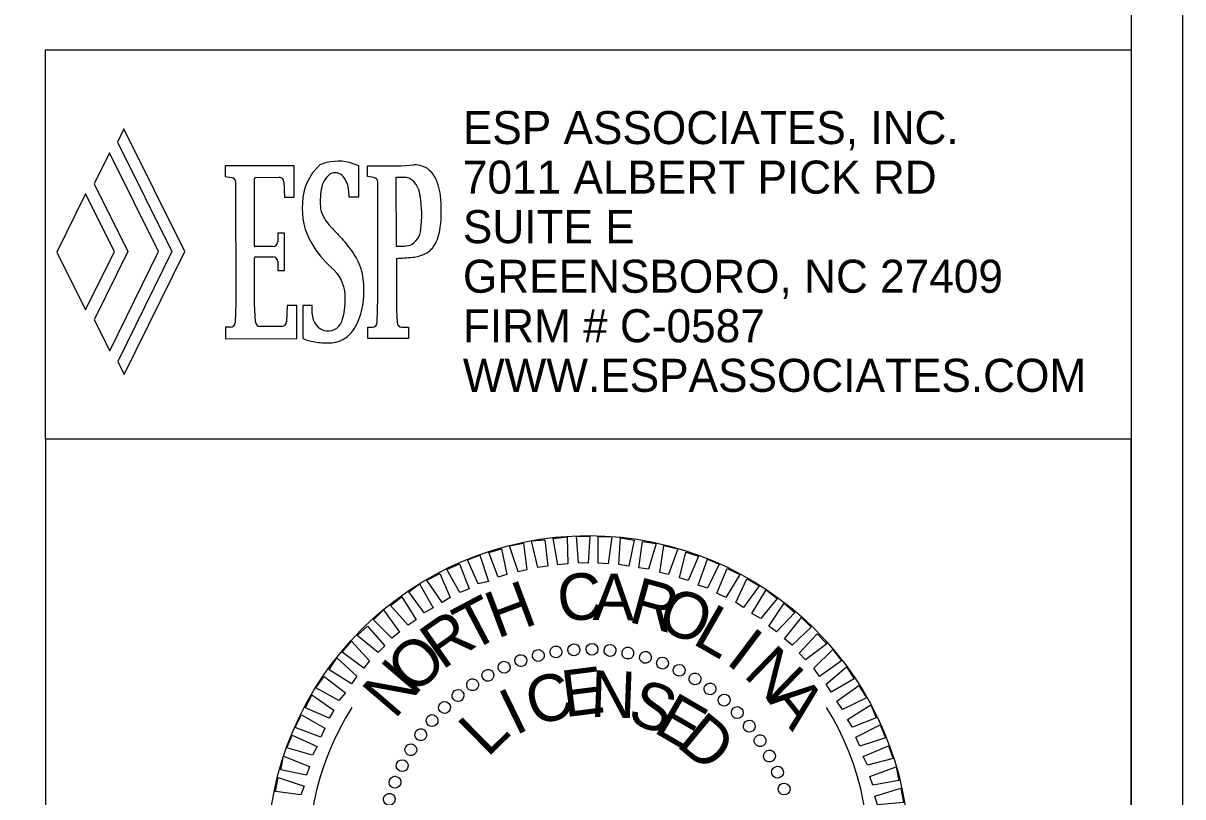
# Model space of a CAD drawing. Extents: x 265553 to 275568, y 168312 to 173522.
# Drawn here: x 268190.7 to 268471.5, y 172334.2 to 172521.6 of the extents above; entities that cross this region are included whole.
import ezdxf

# ---------------------------------------------------------------- set-up
doc = ezdxf.new("R2010")
doc.units = 0
for name, color, linetype in [('Default', 7, 'Continuous'), ('Geotech Sheets and Borders Cell', 7, 'Continuous'), ('Prop Strc Sect_ Border - minor', 7, 'Continuous'), ('Scratch_Level_0', 7, 'Continuous'), ('Scratch_Level_6', 7, 'Continuous'), ('Sheet Plot Border Inside CELL', 7, 'Continuous'), ('Sheet Professional Seal CELL', 7, 'Continuous')]:
    doc.layers.add(name, color=color, linetype=linetype)

msp = doc.modelspace()

# ---------------------------------------------------------------- linework, layer by layer
at = {"layer": 'Default'}
for p, q in [((268271.91, 172487.05), (268269.65, 172487.89)), ((268282.16, 172487.07), (268285.23, 172487.25)), ((268256.25, 172487.04), (268239.59, 172487.02)), ((268239.59, 172487.02), (268239.6, 172484.44)), ((268239.6, 172484.44), (268241.14, 172484.21)), ((268256.26, 172479.43), (268256.25, 172487.04)), ((268271.92, 172479.56), (268271.91, 172487.05)), ((268274.08, 172487.06), (268282.16, 172487.07)), ((268274.08, 172484.48), (268274.08, 172487.06)), ((268275.58, 172484.21), (268274.08, 172484.48)), ((268281.02, 172484.29), (268283.24, 172484.29)), ((268281.04, 172467.5), (268281.02, 172484.29)), ((268242.11, 172483.07), (268242.14, 172453.95)), ((268246.69, 172467.69), (268246.67, 172483.94)), ((268246.98, 172484.25), (268252.66, 172484.26)), ((268253.81, 172483.15), (268253.94, 172479.43)), ((268276.58, 172455.06), (268276.55, 172483.05)), ((268286.3, 172481.53), (268286.83, 172479.69)), ((268253.94, 172479.43), (268256.26, 172479.43)), ((268269.48, 172481.06), (268269.53, 172479.55)), ((268269.53, 172479.55), (268271.92, 172479.56)), ((268253.95, 172470.75), (268252.29, 172470.75)), ((268252.29, 172470.75), (268252.29, 172468.62)), ((268253.96, 172461.69), (268253.95, 172470.75)), ((268251.14, 172467.48), (268246.91, 172467.47)), ((268283, 172467.5), (268281.04, 172467.5)), ((268284.29, 172467.77), (268283, 172467.5)), ((268246.7, 172453.54), (268246.69, 172464.8)), ((268246.91, 172465.02), (268251.15, 172465.02)), ((268281.04, 172464.65), (268281.05, 172452.1)), ((268252.3, 172463.88), (268252.3, 172461.69)), ((268252.3, 172461.69), (268253.96, 172461.69)), ((268242.14, 172453.95), (268241.98, 172449.06)), ((268246.9, 172449.25), (268246.7, 172453.54)), ((268276.38, 172449.1), (268276.58, 172455.06)), ((268254.56, 172453.18), (268254.44, 172449.28)), ((268256.95, 172453.18), (268254.56, 172453.18)), ((268256.95, 172445.19), (268256.95, 172453.18)), ((268260.63, 172453.19), (268258.36, 172453.18)), ((268258.36, 172453.18), (268258.37, 172445.19)), ((268260.63, 172451.19), (268260.63, 172453.19)), ((268281.05, 172452.1), (268281.22, 172449.08)), ((268240.84, 172447.95), (268239.63, 172447.95)), ((268239.63, 172447.95), (268239.64, 172445.17)), ((268253.29, 172448.17), (268248.05, 172448.17)), ((268274.12, 172445.21), (268274.12, 172447.99)), ((268274.12, 172447.99), (268275.23, 172447.99)), ((268282.36, 172448), (268283.96, 172448)), ((268283.96, 172448), (268283.96, 172445.22)), ((268239.64, 172445.17), (268256.95, 172445.19)), ((268283.96, 172445.22), (268274.12, 172445.21))]:
    msp.add_line(p, q, dxfattribs=at)
for points in [[(268213.46, 172492.81), (268226.67, 172466.31), (268213.55, 172439.66), (268215.14, 172436.47), (268229.83, 172466.32), (268215.03, 172496.01), (268213.46, 172492.81)], [(268207.84, 172482.69), (268216.02, 172466.28), (268207.88, 172449.75), (268211.6, 172442.27), (268223.43, 172466.3), (268211.52, 172490.18), (268207.84, 172482.69)], [(268205.74, 172480.29), (268198.78, 172466.15), (268205.77, 172452.13), (268212.73, 172466.27), (268205.74, 172480.29)]]:
    msp.add_lwpolyline(points, dxfattribs=at)
for centre, radius, start, end in [((268271.1, 172477.8), 12.79, 132.277, 178.7717), ((268267.07, 172476.27), 11.9, 77.4945, 112.607), ((268285.56, 172481.83), 5.43, 34.4894, 93.4478), ((268268.49, 172480.56), 5.7, 127.7022, 172.2101), ((268266.19, 172482.77), 2.59, 40.3385, 117.3766), ((268263.94, 172480.86), 5.53, 2.0028, 40.3385), ((268282.49, 172480.38), 3.99, 16.8704, 79.0876), ((268278.26, 172478.17), 13.56, 7.0821, 29.7759), ((268240.97, 172483.07), 1.15, 0.0607, 81.368), ((268246.98, 172483.94), 0.31, 90.0607, 180.0607), ((268252.67, 172483.11), 1.15, 1.9943, 90.0607), ((268275.37, 172483.05), 1.18, 0.0607, 79.8192), ((268279.81, 172478.37), 17.22, 170.1104, 185.809), ((268258.92, 172475.19), 28.27, 352.8067, 9.1634), ((268256.04, 172476.16), 35.87, 353.4945, 5.8911), ((268274.23, 172476.51), 15.99, 174.413, 211.2268), ((268272.23, 172479.19), 9.9, 195.0144, 224.5602), ((268819.02, 172983), 753.4, 222.68215, 223.01817), ((268282.29, 172472.02), 4.69, 295.2092, 355.4805), ((268281.01, 172473.27), 10.73, 328.9362, 353.7339), ((268246.91, 172467.69), 0.22, 180.0607, 270.0607), ((268251.14, 172468.62), 1.15, 270.0607, 0.0607), ((268281.1, 172480.17), 23.76, 210.18, 228.2816), ((268251.2, 172453.16), 23.23, 30.8042, 43.0163), ((268285.62, 172470.63), 5.42, 295.5502, 327.7187), ((268246.91, 172464.8), 0.22, 90.0607, 180.0607), ((268251.15, 172463.87), 1.15, 0.0607, 90.0607), ((268259.62, 172458.06), 13.48, 9.1866, 31.2488), ((268278.09, 172537.43), 72.85, 272.3182, 275.4374), ((268284.16, 172473.67), 8.8, 275.4374, 295.5502), ((268259.54, 172455.38), 9.09, 3.0107, 50.83), ((268249.59, 172456.8), 23.59, 356.494, 8.3188), ((268252.99, 172454.57), 15.68, 343.132, 4.7325), ((268256.42, 172456.03), 16.73, 338.2327, 357.7166), ((268264.73, 172451.14), 4.1, 179.1725, 260.7014), ((268240.83, 172449.1), 1.15, 270.0607, 358.0948), ((268248.05, 172449.32), 1.15, 183.0592, 270.0607), ((268253.29, 172449.32), 1.15, 270.0607, 358.1271), ((268264.52, 172450.59), 3.52, 262.5493, 350.6871), ((268262.09, 172453.45), 10.51, 312.5245, 339.8341), ((268275.23, 172449.14), 1.15, 270.0607, 358.0948), ((268282.36, 172449.14), 1.15, 183.0592, 270.0607), ((268263.52, 172458.35), 14.13, 248.6025, 262.4993), ((268264.81, 172451.31), 7.12, 274.5621, 307.9936), ((268264.2, 172463.79), 19.61, 262.6129, 273.4517)]:
    msp.add_arc(centre, radius, start, end, dxfattribs=at)
at = {"layer": 'Geotech Sheets and Borders Cell'}
msp.add_lwpolyline([(266959.02, 173192.58), (268459.02, 173192.58), (268459.02, 172142.58), (266959.02, 172142.58)], close=True, dxfattribs=at)
msp.add_lwpolyline([(268459.02, 172420.84), (268459.02, 172420.84), (268196.05, 172420.84), (268196.05, 172142.58), (268459.02, 172142.58), (268459.02, 172420.84)], dxfattribs=at)
at = {"layer": 'Scratch_Level_0'}
msp.add_ellipse((268327.53, 172319.79), major_axis=(45.09, 51.04), ratio=0.993455, start_param=1.731198, end_param=5.992706, dxfattribs=at)
at = {"layer": 'Scratch_Level_6'}
msp.add_lwpolyline([(268196.05, 172515.1), (268459.02, 172515.1), (268459.02, 172420.84), (268196.05, 172420.84)], close=True, dxfattribs=at)
msp.add_circle((268327.53, 172319.79), 77.7, dxfattribs=at)
msp.add_circle((268327.53, 172319.79), 77.7, dxfattribs=at)
at = {"layer": 'Sheet Plot Border Inside CELL'}
msp.add_lwpolyline([(266803.85, 172139.74), (268471.52, 172139.74), (268471.52, 173195.41), (266803.85, 173195.41)], close=True, dxfattribs=at)
at = {"layer": 'Sheet Professional Seal CELL'}
for p, q in [((268319.73, 172369.29), (268319.73, 172369.29)), ((268324.03, 172369.89), (268324.03, 172369.89)), ((268328.43, 172369.99), (268328.43, 172369.99)), ((268332.83, 172369.69), (268332.83, 172369.69)), ((268311.13, 172367.29), (268311.13, 172367.29)), ((268315.33, 172368.49), (268315.33, 172368.49)), ((268337.13, 172368.99), (268337.13, 172368.99)), ((268341.33, 172368.09), (268341.33, 172368.09)), ((268345.53, 172366.69), (268345.53, 172366.69)), ((268303.23, 172363.69), (268303.23, 172363.69)), ((268307.13, 172365.69), (268307.13, 172365.69)), ((268349.53, 172364.89), (268349.53, 172364.89)), ((268299.43, 172361.39), (268299.43, 172361.39)), ((268353.43, 172362.89), (268353.43, 172362.89)), ((268295.93, 172358.89), (268295.93, 172358.89)), ((268357.03, 172360.39), (268357.03, 172360.39)), ((268292.63, 172355.89), (268292.63, 172355.89)), ((268360.53, 172357.69), (268360.53, 172357.69)), ((268289.63, 172352.79), (268289.63, 172352.79)), ((268363.63, 172354.69), (268363.63, 172354.69)), ((268366.63, 172351.39), (268366.63, 172351.39)), ((268286.93, 172349.29), (268286.93, 172349.29)), ((268369.13, 172347.89), (268369.13, 172347.89)), ((268284.43, 172345.69), (268284.43, 172345.69)), ((268371.43, 172344.09), (268371.43, 172344.09)), ((268282.43, 172341.79), (268282.43, 172341.79)), ((268373.43, 172340.19), (268373.43, 172340.19)), ((268280.63, 172337.79), (268280.63, 172337.79)), ((268375.03, 172336.19), (268375.03, 172336.19))]:
    msp.add_line(p, q, dxfattribs=at)
for points in [[(268325.13, 172390.89), (268324.63, 172397.39), (268327.93, 172397.29), (268327.53, 172390.79)], [(268329.93, 172390.79), (268329.93, 172397.29), (268333.23, 172397.19), (268332.33, 172390.69)], [(268310.53, 172388.69), (268308.43, 172394.99), (268311.83, 172395.69), (268312.63, 172389.19)], [(268315.33, 172389.79), (268313.73, 172396.19), (268317.03, 172396.49), (268317.73, 172390.09)], [(268320.13, 172390.39), (268319.03, 172396.79), (268322.43, 172397.19), (268322.53, 172390.69)], [(268334.93, 172390.49), (268335.33, 172396.99), (268338.63, 172396.39), (268337.33, 172390.09)], [(268339.73, 172389.69), (268340.63, 172396.09), (268343.93, 172395.59), (268342.13, 172389.39)], [(268344.83, 172388.59), (268345.83, 172395.09), (268349.23, 172394.29), (268346.93, 172388.09)], [(268300.83, 172385.79), (268298.23, 172391.59), (268301.23, 172392.79), (268303.33, 172386.39)], [(268305.73, 172387.39), (268303.43, 172393.39), (268306.53, 172394.29), (268307.83, 172388.09)], [(268349.63, 172387.29), (268351.13, 172393.49), (268354.23, 172392.49), (268351.73, 172386.59)], [(268354.13, 172385.49), (268356.43, 172391.79), (268359.23, 172390.59), (268356.43, 172384.79)], [(268296.43, 172383.69), (268293.23, 172389.29), (268296.33, 172390.69), (268298.63, 172384.59)], [(268358.63, 172383.59), (268361.13, 172389.49), (268364.23, 172388.09), (268360.83, 172382.49)], [(268292.13, 172381.29), (268288.43, 172386.69), (268291.53, 172388.29), (268294.03, 172382.49)], [(268363.23, 172381.29), (268365.93, 172386.99), (268368.93, 172385.29), (268365.13, 172380.09)], [(268287.73, 172378.79), (268284.03, 172383.89), (268286.63, 172385.79), (268289.93, 172379.99)], [(268367.13, 172378.59), (268370.63, 172384.39), (268373.23, 172382.29), (268369.33, 172377.39)], [(268283.93, 172375.79), (268279.63, 172380.59), (268282.33, 172382.69), (268285.83, 172377.09)], [(268371.23, 172375.59), (268374.93, 172381.09), (268377.53, 172378.89), (268373.13, 172374.19)], [(268279.93, 172372.69), (268275.53, 172377.09), (268277.93, 172379.49), (268281.83, 172374.09)], [(268375.03, 172372.49), (268379.13, 172377.69), (268381.53, 172375.29), (268376.93, 172370.99)], [(268276.63, 172369.19), (268271.53, 172373.29), (268274.03, 172375.59), (268278.23, 172370.79)], [(268378.63, 172368.99), (268382.93, 172373.69), (268385.33, 172371.29), (268380.13, 172367.39)], [(268273.13, 172365.39), (268267.93, 172369.29), (268270.13, 172371.89), (268274.53, 172367.19)], [(268382.13, 172365.39), (268386.73, 172369.89), (268388.83, 172367.19), (268383.53, 172363.39)], [(268270.13, 172361.59), (268264.73, 172364.99), (268266.63, 172367.89), (268271.43, 172363.49)], [(268385.13, 172361.49), (268390.03, 172365.69), (268391.93, 172362.79), (268386.33, 172359.59)], [(268267.13, 172357.59), (268261.53, 172360.59), (268263.53, 172363.39), (268268.73, 172359.39)], [(268387.73, 172357.39), (268393.03, 172361.19), (268394.93, 172358.19), (268389.13, 172355.39)], [(268264.73, 172353.29), (268259.03, 172355.79), (268260.53, 172358.89), (268265.93, 172355.19)], [(268390.33, 172352.99), (268395.93, 172356.49), (268397.23, 172353.39), (268391.53, 172351.09)], [(268262.73, 172348.69), (268256.53, 172350.99), (268258.03, 172354.09), (268263.73, 172350.89)], [(268392.33, 172348.69), (268398.23, 172351.69), (268399.53, 172348.49), (268393.33, 172346.49)], [(268260.73, 172344.29), (268254.53, 172346.09), (268255.83, 172349.19), (268261.83, 172346.39)], [(268259.23, 172339.49), (268253.03, 172340.79), (268253.73, 172344.09), (268260.03, 172341.59)], [(268394.13, 172343.99), (268400.23, 172346.59), (268401.33, 172343.49), (268395.13, 172341.89)], [(268395.73, 172339.19), (268402.13, 172341.49), (268402.73, 172338.19), (268396.43, 172337.09)], [(268257.93, 172334.69), (268251.73, 172335.49), (268252.43, 172338.89), (268258.73, 172336.79)], [(268396.93, 172334.39), (268403.23, 172336.29), (268403.83, 172332.89), (268397.53, 172332.29)]]:
    msp.add_lwpolyline(points, close=True, dxfattribs=at)
for centre, major_axis in [((268315.4, 172368.46), (-0.35, 1.4)), ((268319.69, 172369.33), (-0.23, 1.42)), ((268324.03, 172369.83), (-0.1, 1.44)), ((268328.41, 172369.94), (0.03, 1.44)), ((268332.78, 172369.68), (0.15, 1.43)), ((268337.1, 172369.03), (0.27, 1.41)), ((268341.36, 172368.01), (0.4, 1.38)), ((268307.13, 172365.61), (-0.59, 1.32)), ((268311.2, 172367.22), (-0.47, 1.36)), ((268345.51, 172366.62), (0.52, 1.34)), ((268349.52, 172364.87), (0.63, 1.29)), ((268303.21, 172363.66), (-0.7, 1.26)), ((268353.37, 172362.79), (0.74, 1.23)), ((268299.48, 172361.37), (-0.81, 1.19)), ((268357.02, 172360.37), (0.85, 1.16)), ((268295.97, 172358.77), (-0.91, 1.12)), ((268360.44, 172357.65), (0.94, 1.09)), ((268292.69, 172355.87), (-1, 1.04)), ((268363.61, 172354.63), (1.04, 1)), ((268289.68, 172352.7), (-1.09, 0.94)), ((268366.51, 172351.36), (1.12, 0.91)), ((268286.95, 172349.27), (-1.16, 0.85)), ((268369.12, 172347.84), (1.19, 0.81)), ((268284.54, 172345.62), (-1.23, 0.74)), ((268371.4, 172344.11), (1.26, 0.7)), ((268282.45, 172341.78), (-1.29, 0.63)), ((268373.36, 172340.19), (1.32, 0.59)), ((268280.7, 172337.77), (-1.34, 0.52)), ((268374.96, 172336.12), (1.36, 0.47)), ((268279.32, 172333.62), (-1.38, 0.4))]:
    msp.add_ellipse(centre, major_axis=major_axis, ratio=0.999708, dxfattribs=at)

# ---------------------------------------------------------------- texts
at = {"layer": 'Prop Strc Sect_ Border - minor'}
for s, p in [('ESP ASSOCIATES, INC.', (268297.15, 172492.31)), ('7011 ALBERT PICK RD', (268297.15, 172480.31)), ('SUITE E', (268297.15, 172468.31)), ('GREENSBORO, NC 27409 ', (268297.15, 172456.31)), ('FIRM # C-0587', (268297.15, 172444.31)), ('WWW.ESPASSOCIATES.COM', (268297.15, 172432.31))]:
    msp.add_text(s, height=8, dxfattribs=at).set_placement(p)
at = {"layer": 'Sheet Professional Seal CELL'}
for s, rotation, p in [('H', 20.6195, (268305.43, 172372.49)), ('C', 6.2199, (268320.63, 172376.49)), ('A', 359.0203, (268328.53, 172377.09)), ('R', 344.6211, (268336.93, 172376.69)), ('T', 27.8198, (268298.93, 172369.19)), ('O', 337.4212, (268343.63, 172375.19)), ('L', 330.2209, (268352.43, 172371.49)), ('R', 35.0205, (268292.13, 172364.79)), ('I', 323.0201, (268360.53, 172366.69)), ('O', 42.2217, (268285.23, 172358.59)), ('N', 315.8189, (268364.83, 172363.59)), ('N', 49.4235, (268280.63, 172352.79)), ('C', 16.6111, (268314.36, 172351.19)), ('E', 7.2556, (268321.84, 172353.48)), ('N', 357.9004, (268327.92, 172353.63)), ('S', 339.1896, (268336.59, 172352.63)), ('A', 308.6172, (268370.73, 172357.69)), ('I', 25.967, (268309.81, 172348.97)), ('E', 329.8335, (268342.96, 172350.07)), ('L', 44.6812, (268303.12, 172343.57)), ('D', 320.4766, (268348.55, 172346.69))]:
    msp.add_text(s, height=11.28, rotation=rotation, dxfattribs=at).set_placement(p)

doc.saveas('drawing.dxf')
